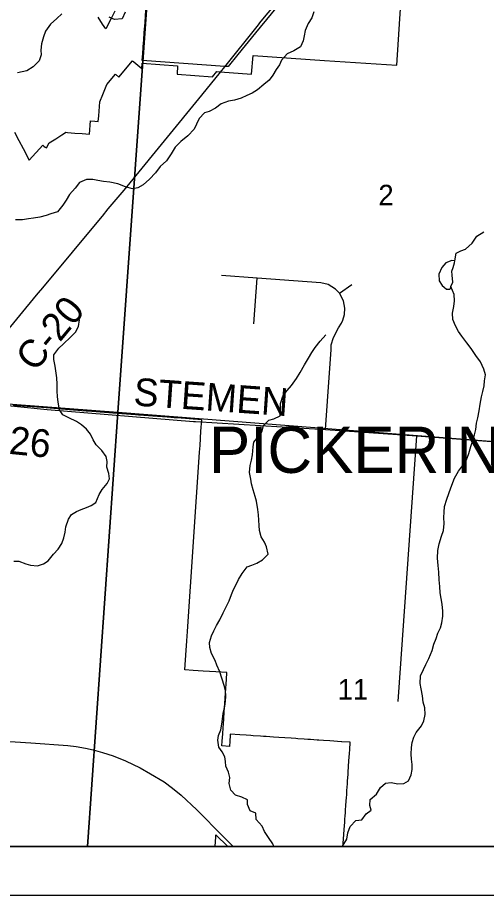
# Model space of a CAD drawing. Extents: x 0 to 34, y 0 to 26.1.
# Drawn here: x 27.339 to 28.299, y 14 to 15.797 of the extents above; entities that cross this region are included whole.
import ezdxf

# ---------------------------------------------------------------- set-up
doc = ezdxf.new("R2010")
doc.units = 0
for name, color, linetype in [('GM_X_Corporation_Text', 7, 'Continuous'), ('GM_X_County_Road', 7, 'Continuous'), ('GM_X_County_Road_Text', 7, 'Continuous'), ('GM_X_Minor_Lake', 7, 'Continuous'), ('GM_X_Minor_River', 7, 'Continuous'), ('GM_X_Section', 7, 'Continuous'), ('GM_X_Section_Text', 7, 'Continuous'), ('GM_X_State_Route', 7, 'Continuous'), ('GM_X_Township_Road', 7, 'Continuous'), ('GM_X_Township_Road_Text', 7, 'Continuous'), ('SC_Scratch1', 7, 'Continuous'), ('SH_Data', 7, 'Continuous')]:
    doc.layers.add(name, color=color, linetype=linetype)

msp = doc.modelspace()

# ---------------------------------------------------------------- linework, layer by layer
at = {"layer": 'GM_X_County_Road'}
msp.add_line((27.7543, 15.6858), (27.7631, 15.6967), dxfattribs=at)
for points in [[(27.7631, 15.6967), (27.8322, 15.7828), (27.8353, 15.7866), (27.8446, 15.7983), (27.9541, 15.9281), (27.9801, 15.9578), (27.9908, 15.9706)], [(27.2002, 15.0134), (27.3778, 15.2289), (27.3819, 15.2336), (27.3907, 15.2442), (27.512, 15.3902), (27.5127, 15.3911), (27.5248, 15.4055), (27.557, 15.4437), (27.5634, 15.4514), (27.5696, 15.4591), (27.7165, 15.6388), (27.7543, 15.6858)]]:
    msp.add_lwpolyline(points, dxfattribs=at)
at = {"layer": 'GM_X_Minor_Lake'}
for points in [[(28.2263, 15.2466), (28.2301, 15.2553), (28.2288, 15.2697), (28.2285, 15.2784), (28.2312, 15.2856), (28.2336, 15.2951), (28.234, 15.2992), (28.228, 15.3001), (28.2158, 15.2949), (28.2077, 15.2855), (28.2015, 15.2723), (28.2021, 15.2586), (28.2085, 15.2487), (28.2126, 15.2452), (28.2171, 15.241)], [(28.2171, 15.241), (28.2238, 15.2413), (28.2255, 15.2427), (28.2263, 15.2466)]]:
    msp.add_lwpolyline(points, dxfattribs=at)
at = {"layer": 'GM_X_Minor_River'}
for points in [[(27.4296, 15.8048), (27.4192, 15.7954), (27.4066, 15.7842), (27.3962, 15.7698), (27.3919, 15.7581), (27.388, 15.7437), (27.3867, 15.7305), (27.3874, 15.721), (27.3835, 15.7089), (27.3708, 15.6965), (27.3582, 15.6886), (27.3487, 15.6865), (27.3389, 15.6843)], [(27.5595, 15.8087), (27.553, 15.7948), (27.5374, 15.7934), (27.5269, 15.7985)], [(27.9456, 15.8089), (27.9413, 15.7968), (27.9343, 15.7851), (27.9277, 15.7708), (27.9261, 15.7598), (27.9241, 15.7495), (27.9183, 15.7378), (27.9045, 15.7293), (27.8912, 15.7233), (27.8793, 15.7105), (27.8751, 15.7007), (27.8685, 15.6909), (27.862, 15.6796), (27.8539, 15.6694), (27.8432, 15.6601), (27.8306, 15.6492), (27.8195, 15.6428), (27.8085, 15.6377), (27.7967, 15.6321), (27.7834, 15.628), (27.7709, 15.6263), (27.756, 15.6211), (27.7442, 15.6121), (27.7316, 15.6051), (27.7221, 15.6021), (27.7106, 15.5905)], [(27.7106, 15.5905), (27.7052, 15.5791), (27.7009, 15.5689), (27.6875, 15.555), (27.6734, 15.5438), (27.6615, 15.5322), (27.6534, 15.5182), (27.6442, 15.5043), (27.6311, 15.4926), (27.6212, 15.4798), (27.6093, 15.4663), (27.5959, 15.455), (27.5852, 15.4491), (27.5742, 15.4465), (27.5602, 15.4505), (27.544, 15.4567), (27.5281, 15.4603), (27.5149, 15.4616), (27.5036, 15.464), (27.4934, 15.466), (27.4801, 15.4661), (27.4656, 15.4598), (27.4568, 15.4481), (27.4453, 15.435), (27.4383, 15.4233), (27.4314, 15.4135), (27.4207, 15.3999), (27.407, 15.3955), (27.3975, 15.3922), (27.3849, 15.3885), (27.3713, 15.3868), (27.3614, 15.3854), (27.3489, 15.3836), (27.3345, 15.383)], [(28.234, 15.2992), (28.2368, 15.3148), (28.2468, 15.32), (28.2563, 15.3229), (28.2696, 15.3357), (28.2793, 15.3496), (28.2938, 15.359)], [(28.0041, 14.1), (28.0041, 14.1009), (28.0133, 14.1152), (28.0153, 14.1281), (28.02, 14.1409), (28.0319, 14.1533), (28.044, 14.1547), (28.0529, 14.1671), (28.0632, 14.1746), (28.0603, 14.1841), (28.0608, 14.1967), (28.0738, 14.2075), (28.0819, 14.2207), (28.0926, 14.2297), (28.1043, 14.2315), (28.1176, 14.2287), (28.1297, 14.2293), (28.1392, 14.2349), (28.1447, 14.2466), (28.1467, 14.2576), (28.1468, 14.2679), (28.1458, 14.2789), (28.1451, 14.2891), (28.1453, 14.3032), (28.1469, 14.3134), (28.1504, 14.324), (28.1554, 14.3338), (28.1662, 14.347), (28.1708, 14.3572), (28.1733, 14.3704), (28.1727, 14.3841), (28.1697, 14.3959), (28.168, 14.4088), (28.1655, 14.4233), (28.1633, 14.4339), (28.1643, 14.4495), (28.1705, 14.4627), (28.1751, 14.4725), (28.1813, 14.4854), (28.1876, 14.5016), (28.1915, 14.5145), (28.1958, 14.5258), (28.1997, 14.5368), (28.2047, 14.5481), (28.2075, 14.5583), (28.2095, 14.5716), (28.2096, 14.5822), (28.2087, 14.5967), (28.2065, 14.6081), (28.204, 14.6198), (28.2034, 14.6324), (28.2024, 14.6464), (28.2018, 14.662), (28.2004, 14.6757), (28.1987, 14.6905), (28.1992, 14.706), (28.202, 14.7201), (28.2071, 14.7356), (28.211, 14.7469), (28.2123, 14.7617), (28.2121, 14.7735), (28.2122, 14.7849), (28.2135, 14.7962), (28.2178, 14.8114), (28.2221, 14.8227), (28.2264, 14.8348), (28.2334, 14.8545), (28.2419, 14.8684), (28.2523, 14.8823), (28.2584, 14.8922), (28.2627, 14.9046), (28.2674, 14.919), (28.2706, 14.9296), (28.2749, 14.9432), (28.2773, 14.9538), (28.2789, 14.9667), (28.2813, 14.9777), (28.2845, 14.9921), (28.2865, 15.0057), (28.2886, 15.0209), (28.2918, 15.0315), (28.2942, 15.0432), (28.295, 15.0534), (28.297, 15.0656), (28.2938, 15.0774), (28.2867, 15.0922), (28.2774, 15.1056), (28.2677, 15.1201), (28.2591, 15.1316), (28.2487, 15.145), (28.2419, 15.1546), (28.2356, 15.1664), (28.2301, 15.179), (28.2298, 15.1923), (28.2323, 15.2059), (28.2339, 15.2177), (28.2333, 15.2302), (28.2263, 15.2466)], [(27.3311, 14.6847), (27.3414, 14.6846), (27.3557, 14.6788), (27.3655, 14.676), (27.3799, 14.6751), (27.3921, 14.6788), (27.4016, 14.6848), (27.4127, 14.6987), (27.4219, 14.7092), (27.4293, 14.7209), (27.4335, 14.7319), (27.4367, 14.744), (27.438, 14.755), (27.4434, 14.7701), (27.4496, 14.7799), (27.4595, 14.7862), (27.469, 14.7903), (27.4801, 14.7944), (27.49, 14.7984), (27.4995, 14.8044), (27.5061, 14.821), (27.5123, 14.8312), (27.5226, 14.8433), (27.5273, 14.8531), (27.5259, 14.8637), (27.5215, 14.8767), (27.5224, 14.8884), (27.5206, 14.8987), (27.5116, 14.9113), (27.5, 14.9228), (27.494, 14.9328), (27.4881, 14.9442), (27.4799, 14.9549), (27.4701, 14.9634), (27.4596, 14.9703), (27.4438, 14.9777), (27.4317, 14.9843), (27.425, 14.9942), (27.4218, 15.0098), (27.4208, 15.0216), (27.4201, 15.0326), (27.4203, 15.0466), (27.4197, 15.0599), (27.4172, 15.0744), (27.4157, 15.0839), (27.4136, 15.0972), (27.413, 15.1067), (27.4237, 15.1206), (27.4333, 15.1292), (27.4474, 15.1431), (27.4574, 15.1536), (27.4636, 15.165), (27.466, 15.1786)], [(27.8637, 14.1), (27.8617, 14.1058), (27.8531, 14.1188), (27.8449, 14.131), (27.8401, 14.1417), (27.8277, 14.1554), (27.8267, 14.1684), (27.8154, 14.1734), (27.8095, 14.186), (27.8096, 14.1955), (27.7979, 14.2013), (27.7855, 14.2052), (27.7754, 14.2156), (27.7725, 14.2289), (27.7734, 14.2418), (27.7712, 14.2521), (27.7657, 14.2646), (27.7646, 14.2741), (27.7636, 14.284), (27.7576, 14.2939), (27.7513, 14.3035), (27.7488, 14.3176), (27.7504, 14.3274), (27.7551, 14.3391), (27.7575, 14.3505), (27.7587, 14.3611), (27.76, 14.3725), (27.7632, 14.3876), (27.7648, 14.3975), (27.7657, 14.4077), (27.7647, 14.4195), (27.7621, 14.4301), (27.7533, 14.4576), (27.7471, 14.4717), (27.7434, 14.4812), (27.7363, 14.4953), (27.7327, 14.5079), (27.732, 14.5181), (27.736, 14.5314), (27.741, 14.5419), (27.7464, 14.5529), (27.7534, 14.5646), (27.76, 14.5789), (27.7661, 14.591), (27.772, 14.6035), (27.777, 14.6163), (27.7813, 14.6261), (27.7863, 14.6367), (27.7914, 14.6469), (27.7987, 14.659), (27.8091, 14.6725), (27.819, 14.6762), (27.8289, 14.6803), (27.8403, 14.687), (27.8518, 14.6987), (27.8489, 14.7135), (27.8445, 14.7234), (27.8381, 14.7345), (27.8341, 14.747), (27.8335, 14.7577), (27.8332, 14.7683), (27.8326, 14.7793), (27.8308, 14.7903), (27.8279, 14.8071), (27.8254, 14.817), (27.8214, 14.8307), (27.8181, 14.8428), (27.8163, 14.8524), (27.8138, 14.866), (27.8151, 14.8805), (27.8179, 14.891), (27.8203, 14.902), (27.8216, 14.9183), (27.8228, 14.9282), (27.8316, 14.9391), (27.8389, 14.9489), (27.8429, 14.9625), (27.8532, 14.9734), (27.8639, 14.976), (27.8768, 14.9823), (27.8777, 14.9937), (27.8771, 15.0073), (27.8822, 15.0224), (27.891, 15.0341), (27.9002, 15.0439), (27.9098, 15.0586), (27.9175, 15.0707), (27.9264, 15.0865), (27.9349, 15.0997), (27.9415, 15.1114), (27.9484, 15.1216), (27.9584, 15.1351), (27.9699, 15.1479)]]:
    msp.add_lwpolyline(points, dxfattribs=at)
at = {"layer": 'GM_X_Section'}
for points in [[(26.603, 16.0634), (26.6185, 16.0611), (27.1167, 16.0245), (27.6154, 15.9857), (27.5444, 14.9891), (26.5367, 15.0651)], [(26.4732, 14.1), (27.4819, 14.1), (27.5444, 14.9891), (26.5367, 15.0651)], [(27.4819, 14.1), (28.5264, 14.1), (28.5788, 14.9085), (27.5444, 14.9891)]]:
    msp.add_lwpolyline(points, close=True, dxfattribs=at)
msp.add_lwpolyline([(28.6244, 15.7025), (28.5788, 14.9085), (27.5444, 14.9891), (27.6154, 15.9857), (28.1277, 15.9466), (28.3097, 15.9346)], dxfattribs=at)
at = {"layer": 'GM_X_State_Route'}
msp.add_lwpolyline([(27.0608, 14.3321), (27.1814, 14.3243), (27.2164, 14.322), (27.3013, 14.3167), (27.3664, 14.3127), (27.4416, 14.3069), (27.4588, 14.3048), (27.478, 14.3015), (27.4936, 14.2981), (27.5131, 14.293), (27.535, 14.2856), (27.56, 14.2759), (27.5902, 14.2614), (27.6115, 14.2492), (27.6391, 14.2323), (27.6565, 14.2195), (27.6738, 14.2053), (27.706, 14.1756), (27.7598, 14.1208), (27.7803, 14.1)], dxfattribs=at)
at = {"layer": 'GM_X_Township_Road'}
for p, q in [((27.8229, 15.1703), (27.8295, 15.2641)), ((27.9985, 15.2331), (28.0237, 15.2512)), ((28.1185, 14.397), (28.1567, 14.9408))]:
    msp.add_line(p, q, dxfattribs=at)
for points in [[(27.9698, 14.9541), (27.9775, 15.07), (27.981, 15.1168), (27.9814, 15.1272), (27.9859, 15.1426), (27.9958, 15.1623), (28.0021, 15.1719), (28.005, 15.1779), (28.0084, 15.1895), (28.0092, 15.2025), (28.0067, 15.2175), (27.9985, 15.2331), (27.99, 15.2416), (27.9747, 15.2506), (27.9602, 15.2546), (27.9319, 15.2566), (27.8295, 15.2641), (27.7566, 15.2695)], [(27.2002, 15.0134), (27.3122, 15.0037), (27.3994, 14.9952), (27.6991, 14.9704), (27.703, 14.9701)], [(27.703, 14.9701), (27.9698, 14.9541), (28.1567, 14.9408), (28.5805, 14.9091)]]:
    msp.add_lwpolyline(points, dxfattribs=at)
at = {"layer": 'SC_Scratch1'}
for points in [[(27.3326, 15.5628), (27.3414, 15.546), (27.3503, 15.5292), (27.3628, 15.5051), (27.3904, 15.5361), (27.3928, 15.5341), (27.3954, 15.5323), (27.398, 15.5307), (27.4036, 15.5406), (27.4172, 15.5492), (27.4295, 15.5572), (27.4309, 15.558), (27.4379, 15.5625), (27.4411, 15.5622), (27.4562, 15.561), (27.4713, 15.5599), (27.4864, 15.5587), (27.4885, 15.5861), (27.4969, 15.5854), (27.5042, 15.5848), (27.5051, 15.5962), (27.5073, 15.6249), (27.5135, 15.6397), (27.5221, 15.6604), (27.5395, 15.6813), (27.5395, 15.6813), (27.5466, 15.6755), (27.5745, 15.709), (27.5769, 15.707), (27.5933, 15.6934), (27.5939, 15.7037), (27.6667, 15.6985), (27.6655, 15.6815), (27.7384, 15.6763), (27.747, 15.6868), (27.754, 15.6862), (27.8183, 15.6816), (27.8211, 15.7194), (27.9676, 15.7097), (28.1154, 15.6996), (28.1288, 15.9009)], [(27.881, 15.8325), (27.8265, 15.7659), (27.7902, 15.7216), (27.77, 15.6969), (27.7631, 15.6974), (27.5944, 15.7094), (27.5955, 15.7236), (27.5963, 15.7356), (27.5965, 15.7378), (27.5975, 15.7519), (27.5985, 15.7661), (27.6001, 15.7874), (27.6019, 15.8126)], [(27.5383, 15.8104), (27.5304, 15.7953), (27.5194, 15.7745), (27.5131, 15.784), (27.5037, 15.7981)], [(25.4691, 14.1), (27.7436, 14.1), (27.7449, 14.1198), (27.7452, 14.1244), (27.7692, 14.1), (28.0055, 14.1), (28.006, 14.1068), (28.0085, 14.1433), (28.0089, 14.1492), (28.009, 14.1513), (28.0093, 14.1553), (28.0098, 14.1637), (28.0102, 14.1685), (28.0107, 14.1768), (28.0111, 14.1818), (28.012, 14.195), (28.0122, 14.1987), (28.0129, 14.2082), (28.0133, 14.2148), (28.0138, 14.2215), (28.0143, 14.2286), (28.0147, 14.2347), (28.0156, 14.2479), (28.0161, 14.2552), (28.0165, 14.2611), (28.0167, 14.2638), (28.0175, 14.2758), (28.0185, 14.2905), (28.0191, 14.2989), (28.0201, 14.313), (28.0201, 14.3137), (28.0028, 14.3148), (28.0025, 14.3148), (27.9787, 14.3164), (27.9787, 14.3164), (27.9655, 14.3173), (27.9562, 14.3179), (27.9523, 14.3182), (27.939, 14.3191), (27.9335, 14.3195), (27.9258, 14.32), (27.9126, 14.3209), (27.9088, 14.3211), (27.8993, 14.3217), (27.8861, 14.3226), (27.8742, 14.3234), (27.8633, 14.3242), (27.8483, 14.3252), (27.8427, 14.3255), (27.8367, 14.3259), (27.8214, 14.327), (27.8168, 14.3273), (27.8068, 14.3279), (27.7942, 14.3288), (27.7744, 14.3301), (27.7733, 14.3133), (27.7729, 14.3075), (27.7728, 14.3063), (27.7728, 14.3052), (27.7572, 14.3062), (27.758, 14.3162), (27.7592, 14.3311), (27.7599, 14.3429), (27.7611, 14.3611), (27.7621, 14.3763), (27.7632, 14.392), (27.7647, 14.4145), (27.7665, 14.4423), (27.7674, 14.4562), (27.745, 14.4577), (27.719, 14.4594), (27.6983, 14.4608), (27.6817, 14.4619), (27.6824, 14.4723), (27.6837, 14.4922), (27.6856, 14.521), (27.6868, 14.5401), (27.7117, 14.9078), (27.7126, 14.921), (27.7145, 14.9508), (27.716, 14.9739), (27.6998, 14.9751), (27.6983, 14.9752), (27.6747, 14.9769), (27.6741, 14.977), (27.6595, 14.9781), (27.6457, 14.9791), (27.6453, 14.9791), (27.6256, 14.9805), (27.6158, 14.9813), (27.5889, 14.9832), (27.5878, 14.9833), (27.5863, 14.9834), (27.5807, 14.9838), (27.5429, 14.9866), (27.4911, 14.9907), (27.4835, 14.9914), (27.4798, 14.9917), (27.4534, 14.9938), (27.429, 14.9957), (27.3974, 14.9981), (27.3394, 15.0026), (27.33, 15.0033)]]:
    msp.add_lwpolyline(points, dxfattribs=at)
at = {"layer": 'SH_Data'}
for points in [[(23.4167, 21), (30.4167, 21), (30.4167, 14), (23.4167, 14)], [(23.5167, 20.9), (30.3167, 20.9), (30.3167, 14.1), (23.5167, 14.1)]]:
    msp.add_lwpolyline(points, close=True, dxfattribs=at)

# ---------------------------------------------------------------- texts
at = {"layer": 'GM_X_Corporation_Text'}
msp.add_text('PICKERINGTON', height=0.094697, rotation=0, dxfattribs=at).set_placement((27.731, 14.8651))
at = {"layer": 'GM_X_County_Road_Text'}
msp.add_text('C-20', height=0.05682, rotation=50.3717, dxfattribs=at).set_placement((27.3744, 15.0697))
at = {"layer": 'GM_X_Section_Text'}
for s, height, p in [('2', 0.0419, (28.0779, 15.4131)), ('11', 0.04186, (27.9946, 14.4011))]:
    msp.add_text(s, height=height, rotation=0, dxfattribs=at).set_placement(p)
at = {"layer": 'GM_X_Township_Road_Text'}
for s, rotation, p in [('STEMEN', 356.0093, (27.5754, 15.0033)), ('T-226', 354.4014, (27.2065, 14.9154))]:
    msp.add_text(s, height=0.05682, rotation=rotation, dxfattribs=at).set_placement(p)

doc.saveas('drawing.dxf')
